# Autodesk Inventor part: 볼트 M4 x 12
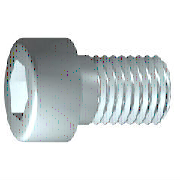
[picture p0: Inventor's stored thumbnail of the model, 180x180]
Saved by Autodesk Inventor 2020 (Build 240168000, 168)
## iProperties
IsCustomPart: 0
Created: 2012-02
Part Number: 볼트 M4 x 12
Material: 강철, 연강
Description: 6각 소켓 머리 캡 나사
Document SubType Name: Modeling
Standard: ISO 4762
Designer: mduedu
Standard Revision: Fourth edition 2004-03-01
Standards Organization: ISO
Language: ko-KR
Size Designation: M4 x 12
Categories: <MemberInstance><Categories><Category DisplayName="조임쇠" InternalName="e4da775c-781d-43d5-af7c-5136215cf5a6" Mnemonic="FSTN"><Category DisplayName="볼트" InternalN
Density: 7.75 g/cm^3
Appearance: 강철
Author: mduedu
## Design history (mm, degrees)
sketch "스케치1"
  geometry: L1 (-1, 0)-(12, 0); L2 (12, 0)-(12, 2); L3 (12, 2)-(1.75, 2); L4 (1.75, 2)-(1.32, 2); L5 (1.32, 2)-(0, 2); L6 (0, 2)-(0, 3.5); L7 (0, 3.5)-(-4, 3.5); L8 (-4, 3.5)-(-4, 1.732); L9 (-4, 1.732)-(-2, 1.732); L10 (-2, 1.732)-(-1, 0); L11 (-7.2, 0)-(15.2, 0) reference; L12 (0, -0.7)-(0, 4.2) reference; L13 (1.75, 2)-(0, 2)
  constraints: 22 end point, 6 parallel, 2 collinear, 2 perpendicular, 1 horizontal, 1 point on line
  dimensions: "d1" = 10.25 distance from line of L3.end L2 (= GEL); "d2" = 0.42952 distance of L4.end L3.end (computed from GAL); "d3" = 4 distance between parallel lines of L8 L6 (= KOH); "d4" = 2 distance of L8.end L9.end (= INTI); "d5" = 60 deg angle of L10 L1; "d6" = 4 diameter of L3 L1 (= GD); "d7" = 4 diameter of L5 L1 (= BDM); "d8" = 3.4641 diameter of L9 L1 (= 1.1547 x SW); "d9" = 7 diameter of L7 L1 (= KOD); "d26" = 12 distance between parallel lines of L12 L2 (= NLG)
revolve "본체" sketch "스케치1" stored, may be unused: angle "d10" = 90 deg
sketch "스케치2"
  geometry: L1 (0, -4.9)-(0, 4.9) reference; L2 (-4.9, 0)-(4.9, 0) reference; L3 (1.732, 0)-(0.866, -1.5); L4 (0.866, -1.5)-(-0.866, -1.5); L5 (-0.866, -1.5)-(-1.732, 0); L6 (-1.732, 0)-(-0.866, 1.5); L7 (-0.866, 1.5)-(0.866, 1.5); L8 (0.866, 1.5)-(1.732, 0); 2 further points
  constraints: 12 end point, 1 coincident, 1 horizontal alignment, 1 point on line, 12 other
extrude "슬롯" join sketch "스케치2" stored distance "d11" = 10; taper "d12" = 0 deg
workplane "Work Plane1"
fillet "Fillet2" dims "d30" = 0.1 (= R)
body "Solid1"
fillet "모깎기1" dims "d17" = 0.4 (= RR)
feature "스레드" dims "d13" = 10.25 (= GEL), "d14" = 0
chamfer "모따기1" distance "d15" = 0.42941 (= -0.5 x SPD + 0.5 x GD); stored, may be unused: second distance "d16" = 0.42941 (= GUL), angle "d27" = 45 deg
other parameters: "GD" = 4 [user parameter; used in 2 equation terms], "NLG" = 12 [user parameter; used in 1 equation term], "GEL" = 10.25 [user parameter; used in 2 equation terms], "KOD" = 7 [user parameter; used in 1 equation term], "KOH" = 4 [user parameter; used in 1 equation term], "INTI" = 2 [user parameter; used in 1 equation term], "GAL" = 0.42941 (= 0.61345 x PTC) [user parameter; used in 1 equation term], "GUL" = 0.42941 (= 0.61345 x PTC) [user parameter; used in 1 equation term], "BDM" = 4 (= NND) [user parameter; used in 1 equation term], "SW" = 3 [user parameter; used in 2 equation terms], "RR" = 0.4 [user parameter; used in 1 equation term], "SPD" = 3.14117 (= NND - 1.2269 x PTC) [user parameter; used in 1 equation term], "d19" = 0, "d28" = 0, "d29" = 0, "R" = 0.1 [user parameter; used in 1 equation term], "TOA" = 30 deg [user parameter], "GD1" = 3.14117 (= THREADDIA - 1.2269 x PTC) [user parameter], "THREADDIA" = 4 [user parameter; used in 1 equation term], "FAWI" = 45 deg [user parameter], "TPU" = 14.28571 (computed from PTC) [user parameter], "PTC" = 0.7 [user parameter; used in 5 equation terms], "NND" = 4 [user parameter; used in 2 equation terms], "E0" = 3.465 (= 1.155 x SW) [user parameter]
